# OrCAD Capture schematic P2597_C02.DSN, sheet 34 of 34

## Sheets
34 34_REVISION HISTORY
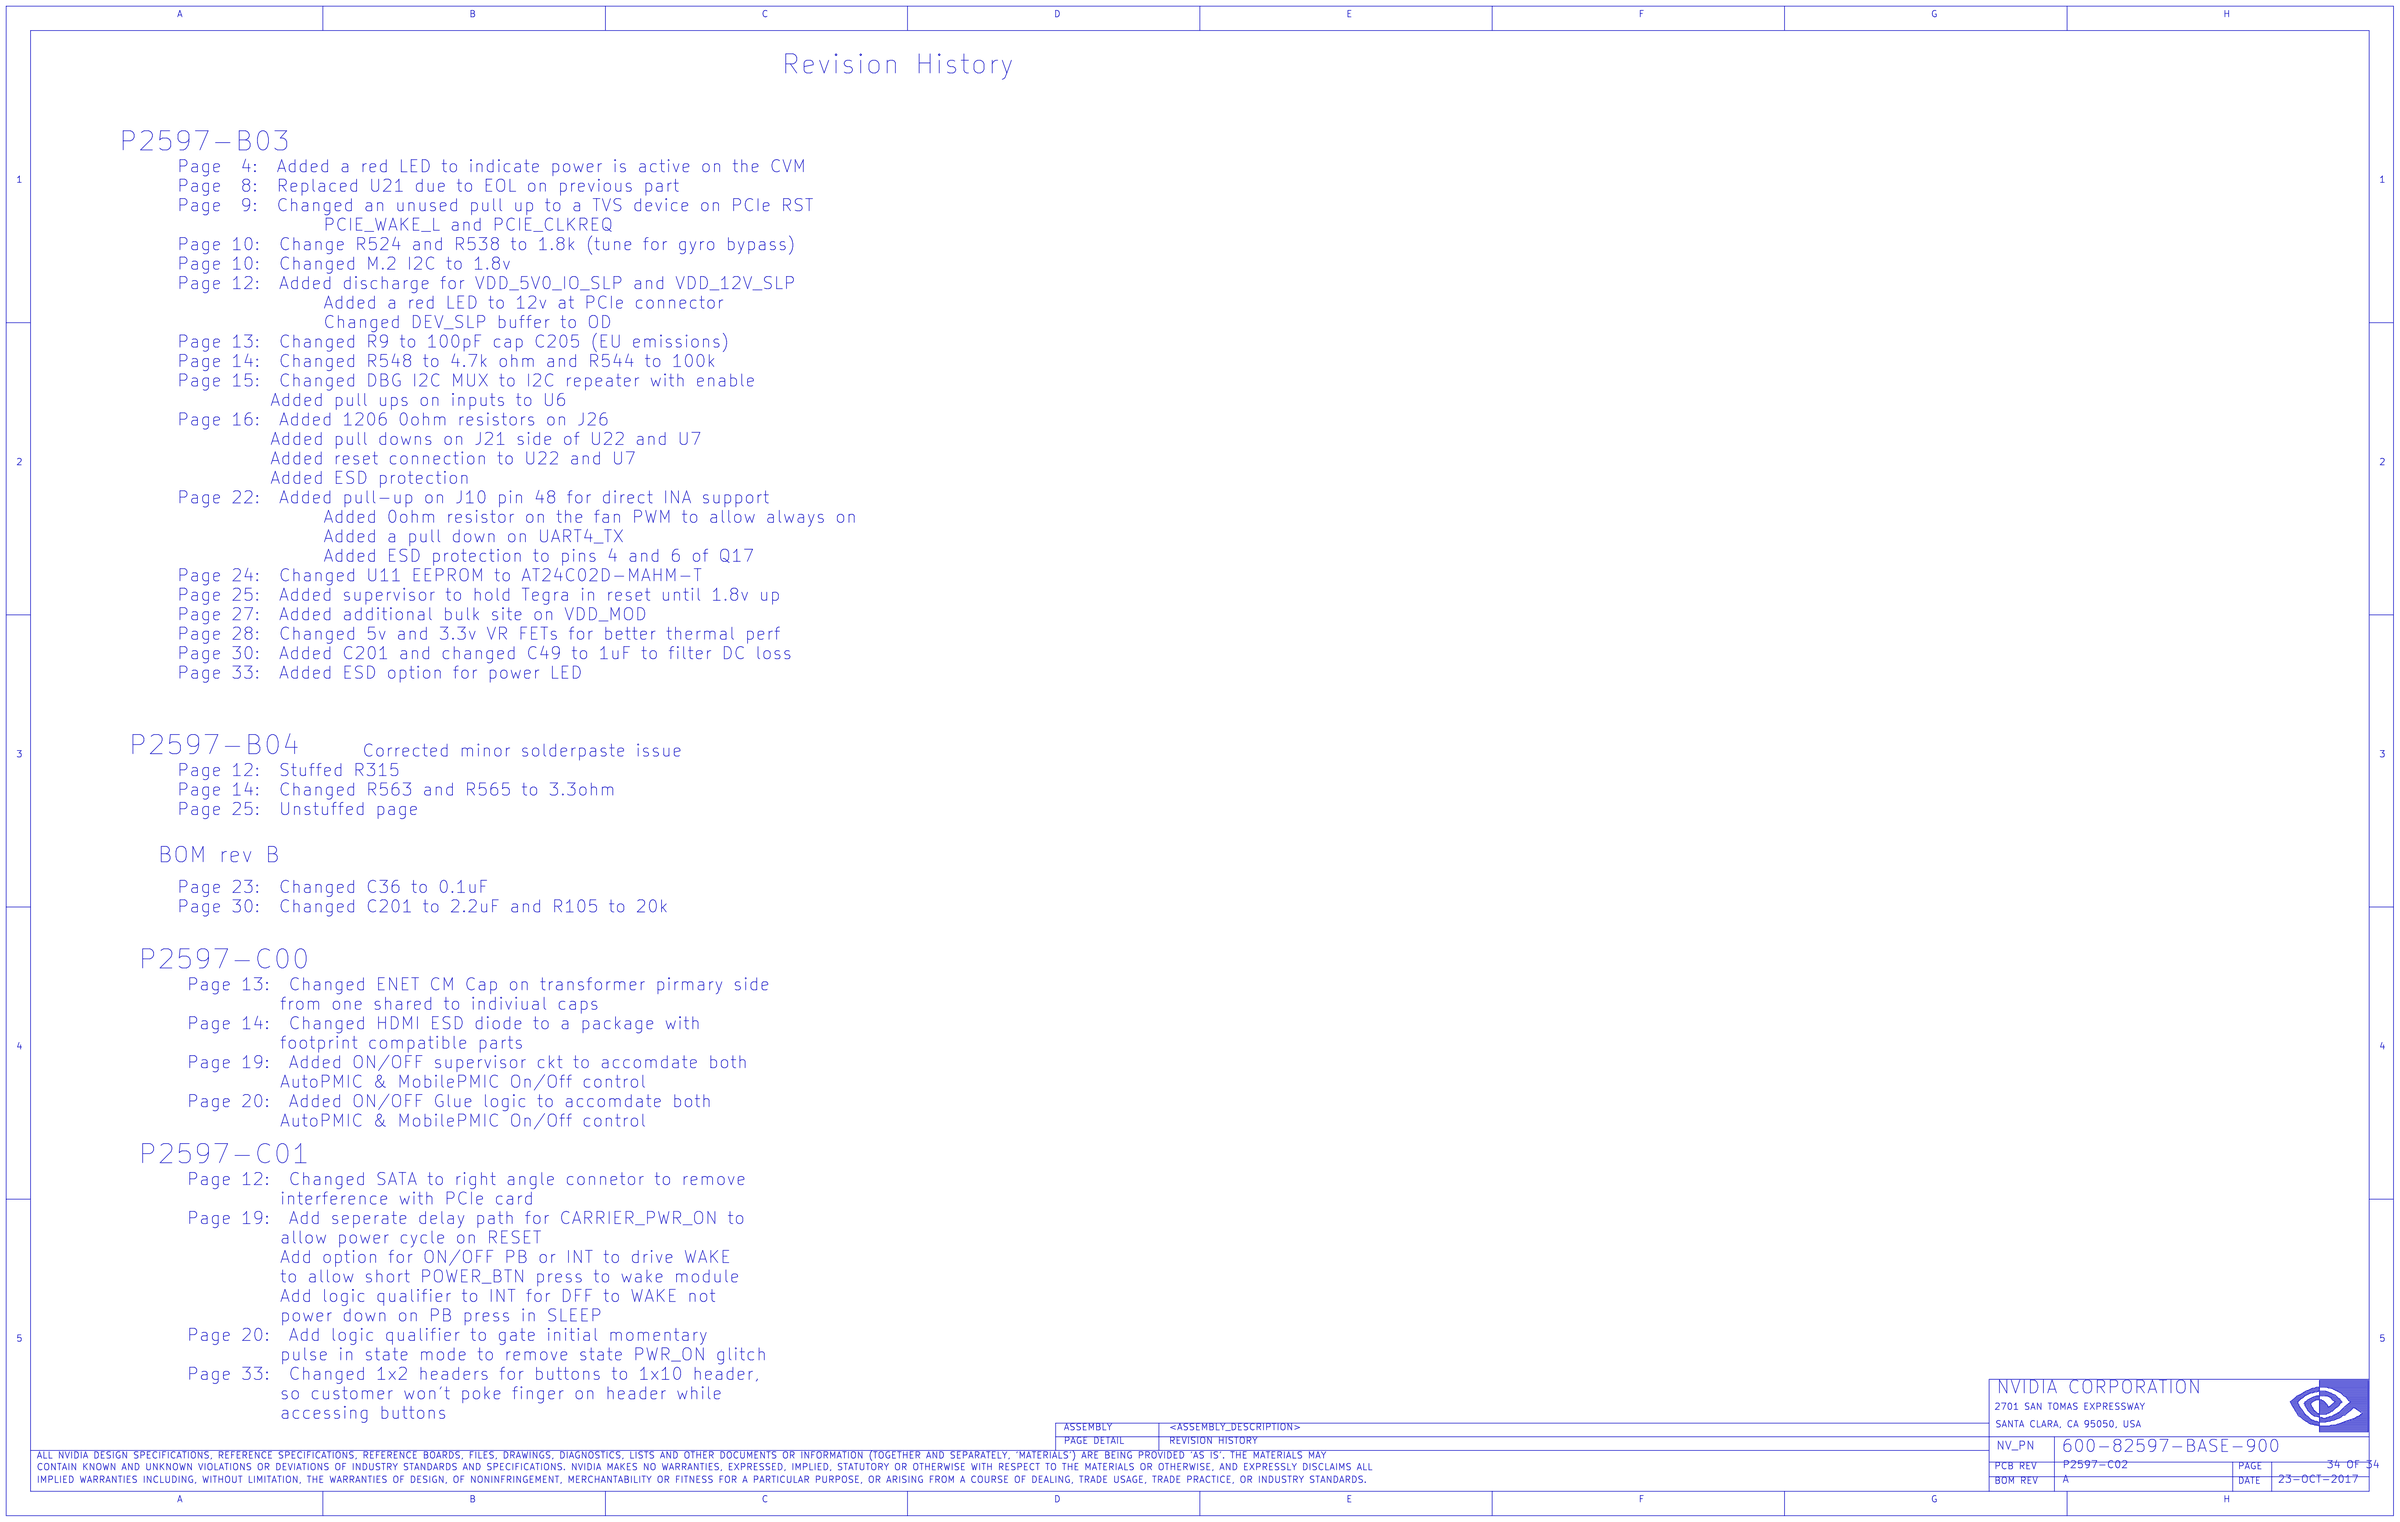
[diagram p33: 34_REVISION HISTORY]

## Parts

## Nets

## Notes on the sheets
sheet 34
- A
- B
- C
- D
- E
- F
- G
- H
- Revision History
- P2597-B03
- Page  4:  Added a red LED to indicate power is active on the CVM
- 1
- Page  8:  Replaced U21 due to EOL on previous part
- 1
- Page  9:  Changed an unused pull up to a TVS device on PCIe RST
- PCIE_WAKE_L and PCIE_CLKREQ
- Page 10:  Change R524 and R538 to 1.8k (tune for gyro bypass)
- Page 10:  Changed M.2 I2C to 1.8v
- Page 12:  Added discharge for VDD_5V0_IO_SLP and VDD_12V_SLP
- Added a red LED to 12v at PCIe connector
- Changed DEV_SLP buffer to OD
- Page 13:  Changed R9 to 100pF cap C205 (EU emissions)
- Page 14:  Changed R548 to 4.7k ohm and R544 to 100k
- Page 15:  Changed DBG I2C MUX to I2C repeater with enable
- Added pull ups on inputs to U6
- Page 16:  Added 1206 0ohm resistors on J26
- Added pull downs on J21 side of U22 and U7
- 2
- Added reset connection to U22 and U7
- 2
- Added ESD protection
- Page 22:  Added pull-up on J10 pin 48 for direct INA support
- Added 0ohm resistor on the fan PWM to allow always on
- Added a pull down on UART4_TX
- Added ESD protection to pins 4 and 6 of Q17
- Page 24:  Changed U11 EEPROM to AT24C02D-MAHM-T
- Page 25:  Added supervisor to hold Tegra in reset until 1.8v up
- Page 27:  Added additional bulk site on VDD_MOD
- Page 28:  Changed 5v and 3.3v VR FETs for better thermal perf
- Page 30:  Added C201 and changed C49 to 1uF to filter DC loss
- Page 33:  Added ESD option for power LED
- P2597-B04
- Corrected minor solderpaste issue
- 3
- 3
- Page 12:  Stuffed R315
- Page 14:  Changed R563 and R565 to 3.3ohm
- Page 25:  Unstuffed page
- BOM rev B
- Page 23:  Changed C36 to 0.1uF
- Page 30:  Changed C201 to 2.2uF and R105 to 20k
- P2597-C00
- Page 13:  Changed ENET CM Cap on transformer pirmary side
- from one shared to indiviual caps
- Page 14:  Changed HDMI ESD diode to a package with
- 4
- footprint compatible parts
- 4
- Page 19:  Added ON/OFF supervisor ckt to accomdate both
- AutoPMIC & MobilePMIC On/Off control
- Page 20:  Added ON/OFF Glue logic to accomdate both
- AutoPMIC & MobilePMIC On/Off control
- P2597-C01
- Page 12:  Changed SATA to right angle connetor to remove
- interference with PCIe card
- Page 19:  Add seperate delay path for CARRIER_PWR_ON to
- allow power cycle on RESET
- Add option for ON/OFF PB or INT to drive WAKE
- to allow short POWER_BTN press to wake module
- Add logic qualifier to INT for DFF to WAKE not
- power down on PB press in SLEEP
- Page 20:  Add logic qualifier to gate initial momentary
- 5
- 5
- pulse in state mode to remove state PWR_ON glitch
- Page 33:  Changed 1x2 headers for buttons to 1x10 header,
- so customer won't poke finger on header while
- NVIDIA CORPORATION
- accessing buttons
- 2701 SAN TOMAS EXPRESSWAY
- ASSEMBLY
- <ASSEMBLY_DESCRIPTION>
- SANTA CLARA, CA 95050, USA
- PAGE DETAIL
- REVISION HISTORY
- NV_PN
- 600-82597-BASE-900
- ALL NVIDIA DESIGN SPECIFICATIONS, REFERENCE SPECIFICATIONS, REFERENCE BOARDS, FILES, DRAWINGS, DIAGNOSTICS, LISTS AND OTHER DOCUMENTS OR INFORMATION (TOGETHER AND SEPARATELY, 'MATERIALS') ARE BEING PROVIDED 'AS IS'. THE MATERIALS MAY
- CONTAIN KNOWN AND UNKNOWN VIOLATIONS OR DEVIATIONS OF INDUSTRY STANDARDS AND SPECIFICATIONS. NVIDIA MAKES NO WARRANTIES, EXPRESSED, IMPLIED, STATUTORY OR OTHERWISE WITH RESPECT TO THE MATERIALS OR OTHERWISE, AND EXPRESSLY DISCLAIMS ALL
- PCB REV
- P2597-C02
- PAGE
- 34 OF 34
- IMPLIED WARRANTIES INCLUDING, WITHOUT LIMITATION, THE WARRANTIES OF DESIGN, OF NONINFRINGEMENT, MERCHANTABILITY OR FITNESS FOR A PARTICULAR PURPOSE, OR ARISING FROM A COURSE OF DEALING, TRADE USAGE, TRADE PRACTICE, OR INDUSTRY STANDARDS.
- BOM REV
- A
- DATE
- 23-OCT-2017
- A
- B
- C
- D
- E
- F
- G
- H
